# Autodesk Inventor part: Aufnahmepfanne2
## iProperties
Shininess: 64.0
Length Units: 11269
Angle Units: 11279
Time Units: 11290
Mass Units: 11283
Length Display Precision: 3
Angle Display Precision: 2
Compacted: True
Part Number: Aufnahmepfanne2
Document SubType Name: Modeling
Created: 2005-08
Material: Standard
Designer: Kumpf
Density: 0.0
Volumn: 0.0
Area: 0.0
PropertySet Name: Model Information
Control State: 0
Master: False
Checked Out: False
Author: Kumpf
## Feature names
1. Extrusion1
2. Bohrung1 [Hole]
3. Extrusion2
4. Extrusion3
5. Extrusion4
6. Fase1 [Chamfer]
